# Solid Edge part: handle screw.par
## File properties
Title: Handle Screw
Author: Robert a Rhodes jr
Template: Normal.par
Last saved by: CADCIM
Revision: 14
Application: Solid Edge
Accuracy: 0.99
Material: aluminum
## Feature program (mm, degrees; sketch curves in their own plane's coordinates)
sketch for "unnamed Protrusion 1" plane through (0, 0, 0) normal (0, -1, 0) x-axis (1, 0, 0)
  circle centre (0, 0) radius 7.5
extrude "unnamed Protrusion 1" add finite 14 along +normal
sketch for "Hole_1" plane through (0, -14, 0) normal (0, -1, 0) x-axis (1, 0, 0)
  hole centre (0, 0) bore radius 4
hole "Hole_1" diameter 8 finite  VBottomAngle = 120 deg
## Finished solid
Body 1: solid body, 5 faces, 4 edges, 1 vertex.
  Faces by surface: cylinder 2, plane 2, cone 1
  Edges by curve: circle 4
Bounding box of the edges (mm): 15.000 x 14.000 x 15.000, from (-7.5, -14, -7.5) to (7.5, 0, 7.5).
Cylindrical faces by radius (mm): R4 x1, R7.5 x1
Conical faces (half-angle, radius in mm at the cone's reference point): 60 deg R4 x1
Planar faces by outward normal: +y 1, -y 1
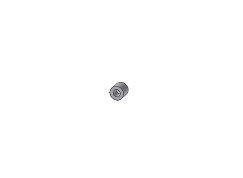
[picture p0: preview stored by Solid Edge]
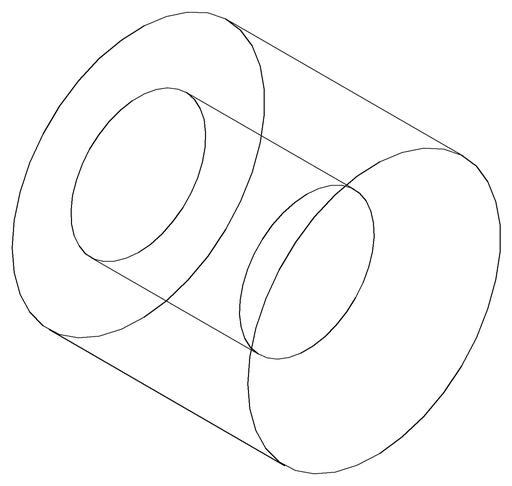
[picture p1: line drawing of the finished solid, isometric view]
